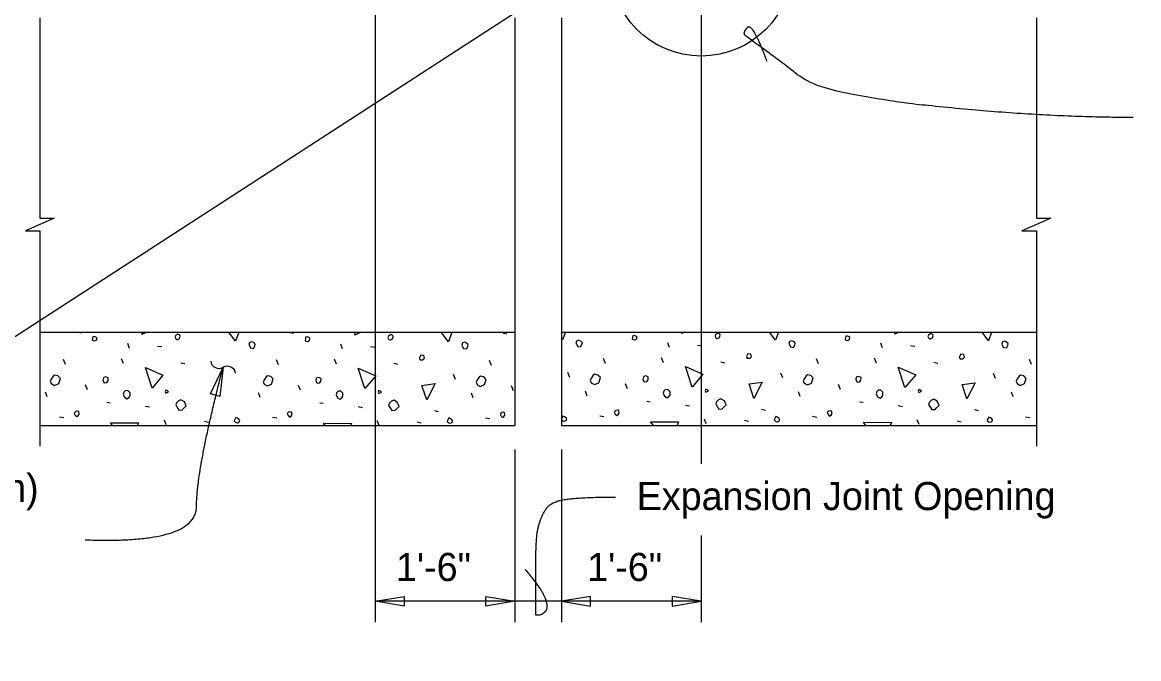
# Model space of a CAD drawing. Extents: x 110698 to 110915, y 110390 to 110472.
# Drawn here: x 110798.34 to 110806.33, y 110409.18 to 110413.74 of the extents above; entities that cross this region are included whole.
import ezdxf

# ---------------------------------------------------------------- set-up
doc = ezdxf.new("R2010")
doc.units = 0
for name, color, linetype in [('AdhocPoint_dp', 7, 'Continuous'), ('Border', 7, 'Continuous'), ('PlotBorder_dp', 7, 'Continuous'), ('SheetBorder_dp', 7, 'Continuous'), ('SheetLines_dp', 7, 'Continuous')]:
    doc.layers.add(name, color=color, linetype=linetype)

msp = doc.modelspace()

# ---------------------------------------------------------------- linework, layer by layer
at = {"layer": 'AdhocPoint_dp'}
for p, q in [((110800.8623, 110422.1361), (110800.8623, 110409.4438)), ((110803.1957, 110422.1361), (110803.1957, 110410.5764)), ((110803.1957, 110410.0632), (110803.1957, 110409.4438))]:
    msp.add_line(p, q, dxfattribs=at)
at = {"layer": 'PlotBorder_dp'}
for p, q in [((110801.8623, 110410.6778), (110801.8623, 110409.4438)), ((110802.1957, 110410.6778), (110802.1957, 110409.4438)), ((110803.1957, 110409.5918), (110800.8623, 110409.5918))]:
    msp.add_line(p, q, dxfattribs=at)
for points in [[(110798.4625, 110413.7679), (110798.4625, 110412.334), (110798.5658, 110412.334), (110798.4625, 110412.289), (110798.3592, 110412.244), (110798.4625, 110412.244), (110798.4625, 110410.7015)], [(110805.5956, 110413.7679), (110805.5956, 110412.334), (110805.6989, 110412.334), (110805.5956, 110412.289), (110805.4922, 110412.244), (110805.5956, 110412.244), (110805.5956, 110410.7015)]]:
    msp.add_lwpolyline(points, dxfattribs=at)
for points in [[(110799.7741, 110411.2675), (110799.7518, 110411.0575), (110799.6839, 110411.0765)], [(110800.8623, 110409.5919), (110801.0706, 110409.6272), (110801.0706, 110409.5566)], [(110801.8623, 110409.5919), (110801.6541, 110409.5566), (110801.6541, 110409.6272)], [(110802.1957, 110409.5919), (110802.4039, 110409.5566), (110802.4039, 110409.6272)], [(110803.1957, 110409.5919), (110802.9874, 110409.6272), (110802.9874, 110409.5566)]]:
    msp.add_lwpolyline(points, close=True, dxfattribs=at)
msp.add_circle((110803.1971, 110414.1476), 0.6527, dxfattribs=at)
for centre, start, end in [((110799.7449, 110411.3186), 188.42943, 300.15665), ((110799.8048, 110411.2155), 8.42943, 120.15665)]:
    msp.add_arc(centre, 0.0596, start, end, dxfattribs=at)
for points in [[(110806.2878, 110413.0551), (110805.6351, 110413.0551), (110804.0743, 110413.2185), (110803.7275, 110413.484), (110803.5293, 110413.6283), (110803.4929, 110413.6589), (110803.5612, 110413.7406), (110803.6657, 110413.4586)], [(110798.7879, 110410.032), (110799.5834, 110410.0022), (110799.5851, 110410.5385), (110799.7742, 110411.2673)], [(110801.9353, 110409.8202), (110802.0534, 110409.684), (110802.1049, 110409.5447), (110802.0564, 110409.4932), (110802.0133, 110409.4932), (110802.0133, 110409.4932), (110802.0133, 110409.7445), (110802.0133, 110410.0474), (110802.0443, 110410.1836), (110802.117, 110410.3078), (110802.3501, 110410.3381), (110802.5832, 110410.3381)]]:
    msp.add_open_spline(points, degree=2, dxfattribs=at)
at = {"layer": 'SheetBorder_dp'}
for p, q in [((110798.738, 110411.5179), (110798.7568, 110411.5141)), ((110800.254, 110411.5159), (110800.2806, 110411.5106)), ((110801.7779, 110411.5124), (110801.8044, 110411.5071)), ((110804.1444, 110411.5179), (110804.1455, 110411.5177)), ((110799.105, 110411.4028), (110799.0926, 110411.4363)), ((110799.3048, 110411.4187), (110799.3366, 110411.4151)), ((110800.6288, 110411.3992), (110800.6164, 110411.4328)), ((110800.8286, 110411.4151), (110800.8604, 110411.4116)), ((110802.97, 110411.4098), (110802.9576, 110411.4434)), ((110803.1697, 110411.4257), (110803.2015, 110411.4222)), ((110804.4938, 110411.4063), (110804.4814, 110411.4399)), ((110804.6935, 110411.4222), (110804.7253, 110411.4187)), ((110798.6471, 110411.2879), (110798.633, 110411.3232)), ((110799.0626, 110411.2932), (110799.0484, 110411.3285)), ((110800.5864, 110411.2896), (110800.5722, 110411.325)), ((110802.5121, 110411.2949), (110802.498, 110411.3303)), ((110802.9275, 110411.3002), (110802.9134, 110411.3356)), ((110804.0359, 110411.2914), (110804.0218, 110411.3267)), ((110804.4513, 110411.2967), (110804.4372, 110411.3321)), ((110805.5597, 110411.2879), (110805.5456, 110411.3232)), ((110799.4727, 110411.3002), (110799.501, 110411.2932)), ((110800.171, 110411.2843), (110800.1568, 110411.3197)), ((110800.9965, 110411.2967), (110801.0248, 110411.2896)), ((110801.6948, 110411.2808), (110801.6806, 110411.3161)), ((110803.3376, 110411.3073), (110803.3659, 110411.3002)), ((110804.8615, 110411.3038), (110804.8897, 110411.2967)), ((110801.4385, 110411.18), (110801.4243, 110411.2154)), ((110802.2558, 110411.1942), (110802.2416, 110411.2295)), ((110803.7796, 110411.1906), (110803.7654, 110411.226)), ((110805.3034, 110411.1871), (110805.2893, 110411.2224)), ((110798.5163, 110411.0545), (110798.504, 110411.0881)), ((110798.8045, 110411.1058), (110798.7903, 110411.1411)), ((110800.0402, 110411.051), (110800.0278, 110411.0846)), ((110800.3283, 110411.1022), (110800.3142, 110411.1376)), ((110801.564, 110411.0474), (110801.5516, 110411.081)), ((110801.8521, 110411.0987), (110801.838, 110411.1341)), ((110802.3813, 110411.0616), (110802.3689, 110411.0952)), ((110802.6694, 110411.1128), (110802.6553, 110411.1482)), ((110803.9051, 110411.058), (110803.8927, 110411.0916)), ((110804.1932, 110411.1093), (110804.1791, 110411.1447)), ((110805.4289, 110411.0545), (110805.4165, 110411.0881)), ((110798.9424, 110411.0174), (110798.9671, 110411.0139)), ((110800.4662, 110411.0139), (110800.4909, 110411.0103)), ((110802.8073, 110411.0245), (110802.8321, 110411.0209)), ((110804.3311, 110411.0209), (110804.3559, 110411.0174)), ((110799.2181, 110410.9891), (110799.2482, 110410.9838)), ((110800.742, 110410.9856), (110800.772, 110410.9803)), ((110801.2864, 110410.9573), (110801.3147, 110410.9502)), ((110803.0831, 110410.9962), (110803.1131, 110410.9909)), ((110803.6276, 110410.9679), (110803.6558, 110410.9608)), ((110804.6069, 110410.9926), (110804.637, 110410.9873)), ((110805.1514, 110410.9644), (110805.1797, 110410.9573)), ((110798.6047, 110410.9131), (110798.6348, 110410.9078)), ((110799.3666, 110410.8548), (110799.3543, 110410.8883)), ((110799.6406, 110410.8813), (110799.6689, 110410.8742)), ((110800.1285, 110410.9096), (110800.1586, 110410.9043)), ((110800.8904, 110410.8512), (110800.8781, 110410.8848)), ((110801.1644, 110410.8777), (110801.1927, 110410.8707)), ((110801.6524, 110410.906), (110801.6824, 110410.9007)), ((110802.4697, 110410.9202), (110802.4997, 110410.9149)), ((110803.2316, 110410.8618), (110803.2192, 110410.8954)), ((110803.5056, 110410.8883), (110803.5339, 110410.8813)), ((110803.9935, 110410.9166), (110804.0235, 110410.9113)), ((110804.7554, 110410.8583), (110804.743, 110410.8919)), ((110805.0294, 110410.8848), (110805.0577, 110410.8777)), ((110805.5173, 110410.9131), (110805.5474, 110410.9078))]:
    msp.add_line(p, q, dxfattribs=at)
for points in [[(110798.8381, 110411.4611), (110798.8575, 110411.4558), (110798.8699, 110411.4646), (110798.8717, 110411.477), (110798.8681, 110411.4805), (110798.854, 110411.4876), (110798.8416, 110411.4858), (110798.8398, 110411.4735), (110798.8381, 110411.4611)], [(110799.1934, 110411.5018), (110799.1984, 110411.5179)], [(110799.2293, 110411.5179), (110799.1934, 110411.5018)], [(110799.4409, 110411.4664), (110799.4479, 110411.4664), (110799.4621, 110411.4735), (110799.4674, 110411.4894), (110799.4656, 110411.4982), (110799.4515, 110411.5053), (110799.4338, 110411.4947), (110799.4303, 110411.4841), (110799.4338, 110411.4735), (110799.4409, 110411.4664)], [(110799.8634, 110411.454), (110799.8148, 110411.5179)], [(110799.8872, 110411.5179), (110799.8634, 110411.454)], [(110800.3619, 110411.4576), (110800.3813, 110411.4523), (110800.3937, 110411.4611), (110800.3955, 110411.4735), (110800.3919, 110411.477), (110800.3778, 110411.4841), (110800.3654, 110411.4823), (110800.3637, 110411.4699), (110800.3619, 110411.4576)], [(110800.7172, 110411.4982), (110800.7233, 110411.5179)], [(110800.761, 110411.5179), (110800.7172, 110411.4982)], [(110800.9647, 110411.4629), (110800.9718, 110411.4629), (110800.9859, 110411.4699), (110800.9912, 110411.4858), (110800.9894, 110411.4947), (110800.9753, 110411.5018), (110800.9576, 110411.4911), (110800.9541, 110411.4805), (110800.9576, 110411.4699), (110800.9647, 110411.4629)], [(110801.3872, 110411.4505), (110801.336, 110411.5179)], [(110801.4124, 110411.5179), (110801.3872, 110411.4505)], [(110802.2244, 110411.5179), (110802.2045, 110411.4646)], [(110802.703, 110411.4682), (110802.7225, 110411.4629), (110802.7348, 110411.4717), (110802.7366, 110411.4841), (110802.7331, 110411.4876), (110802.7189, 110411.4947), (110802.7066, 110411.4929), (110802.7048, 110411.4805), (110802.703, 110411.4682)], [(110803.0583, 110411.5088), (110803.0611, 110411.5179)], [(110803.0785, 110411.5179), (110803.0583, 110411.5088)], [(110803.3058, 110411.4735), (110803.3129, 110411.4735), (110803.327, 110411.4805), (110803.3323, 110411.4965), (110803.3306, 110411.5053), (110803.3164, 110411.5124), (110803.2988, 110411.5018), (110803.2952, 110411.4911), (110803.2988, 110411.4805), (110803.3058, 110411.4735)], [(110803.7283, 110411.4611), (110803.6852, 110411.5179)], [(110803.7495, 110411.5179), (110803.7283, 110411.4611)], [(110804.2268, 110411.4646), (110804.2463, 110411.4593), (110804.2587, 110411.4682), (110804.2604, 110411.4805), (110804.2569, 110411.4841), (110804.2427, 110411.4911), (110804.2304, 110411.4894), (110804.2286, 110411.477), (110804.2268, 110411.4646)], [(110804.5822, 110411.5053), (110804.586, 110411.5179)], [(110804.6102, 110411.5179), (110804.5822, 110411.5053)], [(110804.8296, 110411.4699), (110804.8367, 110411.4699), (110804.8509, 110411.477), (110804.8562, 110411.4929), (110804.8544, 110411.5018), (110804.8403, 110411.5088), (110804.8226, 110411.4982), (110804.819, 110411.4876), (110804.8226, 110411.477), (110804.8296, 110411.4699)], [(110805.2521, 110411.4576), (110805.2063, 110411.5179)], [(110805.2747, 110411.5179), (110805.2521, 110411.4576)], [(110799.9624, 110411.4222), (110799.9712, 110411.4063), (110799.9924, 110411.4028), (110800.0013, 110411.4187), (110800.0048, 110411.4328), (110799.996, 110411.4417), (110799.98, 110411.4505), (110799.9641, 110411.4452), (110799.9588, 110411.4293), (110799.9624, 110411.4222)], [(110801.4862, 110411.4187), (110801.495, 110411.4028), (110801.5162, 110411.3992), (110801.5251, 110411.4151), (110801.5286, 110411.4293), (110801.5198, 110411.4381), (110801.5039, 110411.447), (110801.488, 110411.4417), (110801.4826, 110411.4257), (110801.4862, 110411.4187)], [(110802.2045, 110411.4646), (110802.1957, 110411.4763)], [(110802.3035, 110411.4328), (110802.3123, 110411.4169), (110802.3336, 110411.4134), (110802.3424, 110411.4293), (110802.3459, 110411.4434), (110802.3371, 110411.4523), (110802.3212, 110411.4611), (110802.3053, 110411.4558), (110802.3, 110411.4399), (110802.3035, 110411.4328)], [(110803.8273, 110411.4293), (110803.8362, 110411.4134), (110803.8574, 110411.4098), (110803.8662, 110411.4257), (110803.8697, 110411.4399), (110803.8609, 110411.4487), (110803.845, 110411.4576), (110803.8291, 110411.4523), (110803.8238, 110411.4363), (110803.8273, 110411.4293)], [(110805.3511, 110411.4257), (110805.36, 110411.4098), (110805.3812, 110411.4063), (110805.39, 110411.4222), (110805.3936, 110411.4363), (110805.3847, 110411.4452), (110805.3688, 110411.454), (110805.3529, 110411.4487), (110805.3476, 110411.4328), (110805.3511, 110411.4257)], [(110801.1839, 110411.3214), (110801.2051, 110411.3214), (110801.2157, 110411.3321), (110801.2104, 110411.3515), (110801.1874, 110411.3533), (110801.1839, 110411.3427), (110801.1786, 110411.3338), (110801.1839, 110411.3214), (110801.1804, 110411.325)], [(110803.525, 110411.3321), (110803.5462, 110411.3321), (110803.5569, 110411.3427), (110803.5515, 110411.3621), (110803.5286, 110411.3639), (110803.525, 110411.3533), (110803.5197, 110411.3444), (110803.525, 110411.3321), (110803.5215, 110411.3356)], [(110805.0488, 110411.3285), (110805.0701, 110411.3285), (110805.0807, 110411.3391), (110805.0754, 110411.3586), (110805.0524, 110411.3603), (110805.0488, 110411.3497), (110805.0435, 110411.3409), (110805.0488, 110411.3285), (110805.0453, 110411.3321)], [(110799.2659, 110411.1182), (110799.2181, 110411.2649), (110799.3436, 110411.2101), (110799.2659, 110411.1182)], [(110800.7897, 110411.1146), (110800.742, 110411.2613), (110800.8675, 110411.2065), (110800.7897, 110411.1146)], [(110803.1308, 110411.1252), (110803.0831, 110411.2719), (110803.2086, 110411.2171), (110803.1308, 110411.1252)], [(110804.6546, 110411.1217), (110804.6069, 110411.2684), (110804.7324, 110411.2136), (110804.6546, 110411.1217)], [(110798.5446, 110411.15), (110798.5676, 110411.1376), (110798.5977, 110411.15), (110798.61, 110411.1871), (110798.5923, 110411.2048), (110798.5694, 110411.2101), (110798.5588, 110411.203), (110798.5464, 110411.1836), (110798.5375, 110411.1676), (110798.5446, 110411.15)], [(110798.9141, 110411.173), (110798.9229, 110411.157), (110798.9424, 110411.1588), (110798.9512, 110411.1712), (110798.953, 110411.1906), (110798.9406, 110411.1959), (110798.9318, 110411.1977), (110798.9212, 110411.1942), (110798.9176, 110411.1906), (110798.9141, 110411.173)], [(110800.0684, 110411.1464), (110800.0914, 110411.1341), (110800.1215, 110411.1464), (110800.1338, 110411.1836), (110800.1162, 110411.2012), (110800.0932, 110411.2065), (110800.0826, 110411.1995), (110800.0702, 110411.18), (110800.0614, 110411.1641), (110800.0684, 110411.1464)], [(110800.4379, 110411.1694), (110800.4467, 110411.1535), (110800.4662, 110411.1553), (110800.475, 110411.1676), (110800.4768, 110411.1871), (110800.4644, 110411.1924), (110800.4556, 110411.1942), (110800.445, 110411.1906), (110800.4414, 110411.1871), (110800.4379, 110411.1694)], [(110801.5922, 110411.1429), (110801.6152, 110411.1305), (110801.6453, 110411.1429), (110801.6577, 110411.18), (110801.64, 110411.1977), (110801.617, 110411.203), (110801.6064, 110411.1959), (110801.594, 110411.1765), (110801.5852, 110411.1606), (110801.5922, 110411.1429)], [(110802.4096, 110411.157), (110802.4326, 110411.1447), (110802.4626, 110411.157), (110802.475, 110411.1942), (110802.4573, 110411.2118), (110802.4343, 110411.2171), (110802.4237, 110411.2101), (110802.4113, 110411.1906), (110802.4025, 110411.1747), (110802.4096, 110411.157)], [(110802.779, 110411.18), (110802.7879, 110411.1641), (110802.8073, 110411.1659), (110802.8162, 110411.1783), (110802.8179, 110411.1977), (110802.8056, 110411.203), (110802.7967, 110411.2048), (110802.7861, 110411.2012), (110802.7826, 110411.1977), (110802.779, 110411.18)], [(110803.5728, 110411.0439), (110803.5392, 110411.1482), (110803.6329, 110411.1606), (110803.5728, 110411.0439)], [(110803.9334, 110411.1535), (110803.9564, 110411.1411), (110803.9864, 110411.1535), (110803.9988, 110411.1906), (110803.9811, 110411.2083), (110803.9581, 110411.2136), (110803.9475, 110411.2065), (110803.9352, 110411.1871), (110803.9263, 110411.1712), (110803.9334, 110411.1535)], [(110804.3028, 110411.1765), (110804.3117, 110411.1606), (110804.3311, 110411.1623), (110804.34, 110411.1747), (110804.3417, 110411.1942), (110804.3294, 110411.1995), (110804.3205, 110411.2012), (110804.3099, 110411.1977), (110804.3064, 110411.1942), (110804.3028, 110411.1765)], [(110805.4572, 110411.15), (110805.4802, 110411.1376), (110805.5102, 110411.15), (110805.5226, 110411.1871), (110805.5049, 110411.2048), (110805.4819, 110411.2101), (110805.4713, 110411.203), (110805.459, 110411.1836), (110805.4501, 110411.1676), (110805.4572, 110411.15)], [(110799.059, 110411.074), (110799.0696, 110411.0527), (110799.0873, 110411.0421), (110799.1015, 110411.0527), (110799.1085, 110411.0634), (110799.1085, 110411.0846), (110799.0926, 110411.1005), (110799.0732, 110411.0987), (110799.0643, 110411.0899), (110799.059, 110411.074)], [(110799.3649, 110411.0828), (110799.3843, 110411.0916), (110799.3772, 110411.0987), (110799.3649, 110411.104), (110799.3596, 110411.0916), (110799.3649, 110411.0828)], [(110800.5829, 110411.0704), (110800.5935, 110411.0492), (110800.6111, 110411.0386), (110800.6253, 110411.0492), (110800.6324, 110411.0598), (110800.6324, 110411.081), (110800.6164, 110411.0969), (110800.597, 110411.0952), (110800.5882, 110411.0863), (110800.5829, 110411.0704)], [(110800.8887, 110411.0793), (110800.9081, 110411.0881), (110800.9011, 110411.0952), (110800.8887, 110411.1005), (110800.8834, 110411.0881), (110800.8887, 110411.0793)], [(110801.2316, 110411.0333), (110801.198, 110411.1376), (110801.2917, 110411.15), (110801.2316, 110411.0333)], [(110802.924, 110411.081), (110802.9346, 110411.0598), (110802.9523, 110411.0492), (110802.9664, 110411.0598), (110802.9735, 110411.0704), (110802.9735, 110411.0916), (110802.9576, 110411.1075), (110802.9381, 110411.1058), (110802.9293, 110411.0969), (110802.924, 110411.081)], [(110803.2298, 110411.0899), (110803.2493, 110411.0987), (110803.2422, 110411.1058), (110803.2298, 110411.1111), (110803.2245, 110411.0987), (110803.2298, 110411.0899)], [(110804.4478, 110411.0775), (110804.4584, 110411.0563), (110804.4761, 110411.0457), (110804.4902, 110411.0563), (110804.4973, 110411.0669), (110804.4973, 110411.0881), (110804.4814, 110411.104), (110804.4619, 110411.1022), (110804.4531, 110411.0934), (110804.4478, 110411.0775)], [(110804.7536, 110411.0863), (110804.7731, 110411.0952), (110804.766, 110411.1022), (110804.7536, 110411.1075), (110804.7483, 110411.0952), (110804.7536, 110411.0863)], [(110805.0966, 110411.0404), (110805.063, 110411.1447), (110805.1567, 110411.157), (110805.0966, 110411.0404)], [(110799.4356, 110410.9979), (110799.4586, 110410.9608), (110799.4815, 110410.9626), (110799.4904, 110410.9714), (110799.5098, 110410.9909), (110799.4974, 110411.0209), (110799.4727, 110411.0351), (110799.455, 110411.028), (110799.4409, 110411.0139), (110799.4356, 110410.9979)], [(110800.9594, 110410.9944), (110800.9824, 110410.9573), (110801.0054, 110410.9591), (110801.0142, 110410.9679), (110801.0336, 110410.9873), (110801.0213, 110411.0174), (110800.9965, 110411.0315), (110800.9788, 110411.0245), (110800.9647, 110411.0103), (110800.9594, 110410.9944)], [(110803.3005, 110411.005), (110803.3235, 110410.9679), (110803.3465, 110410.9697), (110803.3553, 110410.9785), (110803.3748, 110410.9979), (110803.3624, 110411.028), (110803.3376, 110411.0421), (110803.32, 110411.0351), (110803.3058, 110411.0209), (110803.3005, 110411.005)], [(110804.8243, 110411.0015), (110804.8473, 110410.9644), (110804.8703, 110410.9661), (110804.8791, 110410.975), (110804.8986, 110410.9944), (110804.8862, 110411.0245), (110804.8615, 110411.0386), (110804.8438, 110411.0315), (110804.8296, 110411.0174), (110804.8243, 110411.0015)], [(110798.7161, 110410.9255), (110798.7267, 110410.9149), (110798.7373, 110410.9219), (110798.7444, 110410.9325), (110798.7408, 110410.9502), (110798.732, 110410.952), (110798.7196, 110410.9502), (110798.709, 110410.9396), (110798.7161, 110410.9255)], [(110800.2399, 110410.9219), (110800.2505, 110410.9113), (110800.2611, 110410.9184), (110800.2682, 110410.929), (110800.2647, 110410.9467), (110800.2558, 110410.9484), (110800.2434, 110410.9467), (110800.2328, 110410.9361), (110800.2399, 110410.9219)], [(110801.7637, 110410.9184), (110801.7743, 110410.9078), (110801.7849, 110410.9149), (110801.792, 110410.9255), (110801.7885, 110410.9431), (110801.7796, 110410.9449), (110801.7673, 110410.9431), (110801.7567, 110410.9325), (110801.7637, 110410.9184)], [(110802.581, 110410.9325), (110802.5917, 110410.9219), (110802.6023, 110410.929), (110802.6093, 110410.9396), (110802.6058, 110410.9573), (110802.597, 110410.9591), (110802.5846, 110410.9573), (110802.574, 110410.9467), (110802.581, 110410.9325)], [(110804.1049, 110410.929), (110804.1155, 110410.9184), (110804.1261, 110410.9255), (110804.1331, 110410.9361), (110804.1296, 110410.9537), (110804.1208, 110410.9555), (110804.1084, 110410.9537), (110804.0978, 110410.9431), (110804.1049, 110410.929)], [(110798.9837, 110410.8512), (110798.9689, 110410.8707), (110799.1686, 110410.8689), (110799.162, 110410.8512)], [(110799.8651, 110410.8724), (110799.8775, 110410.8707), (110799.8899, 110410.876), (110799.8934, 110410.8866), (110799.8881, 110410.8954), (110799.8775, 110410.9025), (110799.8651, 110410.9078), (110799.8581, 110410.8936), (110799.8545, 110410.883), (110799.8651, 110410.8724)], [(110800.5048, 110410.8512), (110800.4927, 110410.8671), (110800.6925, 110410.8654), (110800.6872, 110410.8512)], [(110801.389, 110410.8689), (110801.4013, 110410.8671), (110801.4137, 110410.8724), (110801.4172, 110410.883), (110801.4119, 110410.8919), (110801.4013, 110410.8989), (110801.389, 110410.9043), (110801.3819, 110410.8901), (110801.3783, 110410.8795), (110801.389, 110410.8689)], [(110802.2063, 110410.883), (110802.2187, 110410.8813), (110802.231, 110410.8866), (110802.2346, 110410.8972), (110802.2293, 110410.906), (110802.2187, 110410.9131), (110802.2063, 110410.9184), (110802.1992, 110410.9043), (110802.1957, 110410.8936), (110802.2063, 110410.883)], [(110802.854, 110410.8512), (110802.8338, 110410.8777), (110803.0336, 110410.876), (110803.0243, 110410.8512)], [(110803.7301, 110410.8795), (110803.7425, 110410.8777), (110803.7548, 110410.883), (110803.7584, 110410.8936), (110803.7531, 110410.9025), (110803.7425, 110410.9096), (110803.7301, 110410.9149), (110803.723, 110410.9007), (110803.7195, 110410.8901), (110803.7301, 110410.8795)], [(110804.3751, 110410.8512), (110804.3576, 110410.8742), (110804.5574, 110410.8724), (110804.5495, 110410.8512)], [(110805.2539, 110410.876), (110805.2663, 110410.8742), (110805.2787, 110410.8795), (110805.2822, 110410.8901), (110805.2769, 110410.8989), (110805.2663, 110410.906), (110805.2539, 110410.9113), (110805.2468, 110410.8972), (110805.2433, 110410.8866), (110805.2539, 110410.876)]]:
    msp.add_lwpolyline(points, dxfattribs=at)
at = {"layer": 'SheetLines_dp'}
for p, q in [((110815.4706, 110422.6259), (110773.7639, 110395.5884)), ((110801.8623, 110413.7679), (110801.8623, 110410.8512)), ((110802.1957, 110413.7679), (110802.1957, 110410.8512)), ((110798.4625, 110411.5179), (110801.8623, 110411.5179)), ((110802.1957, 110411.5179), (110805.5956, 110411.5179)), ((110798.4625, 110410.8512), (110801.8623, 110410.8512)), ((110802.1957, 110410.8512), (110805.5956, 110410.8512))]:
    msp.add_line(p, q, dxfattribs=at)

# ---------------------------------------------------------------- texts
at = {"layer": 'Border'}
for s, p in [('Expansion Joint Opening', (110802.7347, 110410.2447)), ('1\'-6"', (110801.0117, 110409.737)), ('1\'-6"', (110802.3799, 110409.737))]:
    msp.add_text(s, height=0.2016, dxfattribs=at).set_placement(p)
at = {"layer": 'PlotBorder_dp'}
msp.add_text('Bridge Deck (shown)', height=0.2016, dxfattribs=at).set_placement((110795.9521, 110410.3038))

doc.saveas('drawing.dxf')
